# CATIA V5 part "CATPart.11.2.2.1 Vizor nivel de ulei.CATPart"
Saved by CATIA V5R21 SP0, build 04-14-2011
Part number: Vizor nivel de ulei
Bounding box of the stored display mesh (mm): x 0 to 12, y -27.467 to 27.481, z -27.5 to 27.464
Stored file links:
  C:\Users\MIRCEA\Desktop\MOM\Mogan\model\CATPart.11.2.2.1 Vizor nivel de ulei.CATPart
  C:\Program Files (x86)\Dassault Systemes\B21\intel_a\reffiles\standard\MetricThinPitch.txt
  C:\Program Files (x86)\Dassault Systemes\B21\intel_a\reffiles\standard\MetricThickPitch.txt
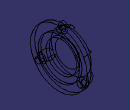
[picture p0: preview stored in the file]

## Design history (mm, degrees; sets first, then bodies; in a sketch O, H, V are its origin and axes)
Parameters
  d = 30 mm
  D = 40 mm
  h = 3 mm
  D1 = 55 mm
  l = 12 mm
AxisSystem1: origin (0, 0, 0), X (1, 0, 0), Y (0, 1, 0), Z (0, 0, 1)
Body1 (main body)
  Sketch1 on xy-plane, origin (0, 0, 0), H (1, 0, 0), V (0, 1, 0)
    line L1 (0, 0) -> (0, 19.5)
    arc A1 centre (8, 19.5) radius 8 from (0, 19.5) to (8, 27.5) cw
    line L2 (8, 27.5) -> (12, 27.5)
    line L3 (12, 27.5) -> (12, 20)
    line L4 (12, 20) -> (9.5, 20)
    line L5 (9.5, 20) -> (9.5, 15)
    line L6 (9.5, 15) -> (6.5, 15)
    arc A2 centre (6.5, 12) radius 3 from (6.5, 15) to (3.5, 12) ccw
    line L7 (3.5, 12) -> (3.5, 0)
    point P11 (3.5, 0)
    line L8 (3.5, 0) -> (0, 0)
    distance L6 L8 = 15 {= d/2}
    distance L4 L8 = 20 {= D/2}
    distance L2 L8 = 27.5 {= D1/2}
    distance L1 L3 = 12 {= l}
    distance L3 L5 = 2.5 {= h - 0.5 mm}
    distance L7 L5 = 6
    radius A1 = 8
    radius A2 = 3
    vertical: L1 V, L3 V, L5 V
    tangency: A1 L1, L2 A1, A2 L6, L7 A2
    horizontal: L4 H, L6 H, L8 H
    coincidence: P11 H
  Shaft1: profile Sketch1, axis Sketch1.L8, angle 360
  Sketch2 on face of Shaft1 from Sketch1.L1, origin (0, 0, 19.5), H (0, 1, 0), V (0, 0, -1)
    point P1 (0, -4.25)
    reference projected point E1 (0, -4.25) from Sketch3.P1
    coincidence: E1 P1
  Hole1: placed by Sketch2, at (0, 0, 23.75) direction (1, 0, 0), diameter 5.5, depth 13, V-bottom angle 120, counterbore diameter 9, counterbore depth 8
  CircPattern1: of Hole1, instances 3, angular step 120 {= 360.0*1 deg/CircPattern1.AngularNumber}, axis from face of Shaft1 from Sketch1.L1
  Sketch3 on yz-plane, origin (0, 0, 0), H (0, 1, 0), V (0, 0, 1)
    point P1 (0, 23.75)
